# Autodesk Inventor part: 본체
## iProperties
Company: 한국ATC센터
Created: 2014-08
Part Number: 본체
Document SubType Name: Modeling
Designer: KYOUNG IL JANG
Density: 1 g/cm^3
Material: 기본값
Mass: 1211.76 g
Surface Area: 1019.41 cm^2
Volume: 447.145 cm^3
Author: KYOUNG IL JANG
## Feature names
1. M4 [Hole]
